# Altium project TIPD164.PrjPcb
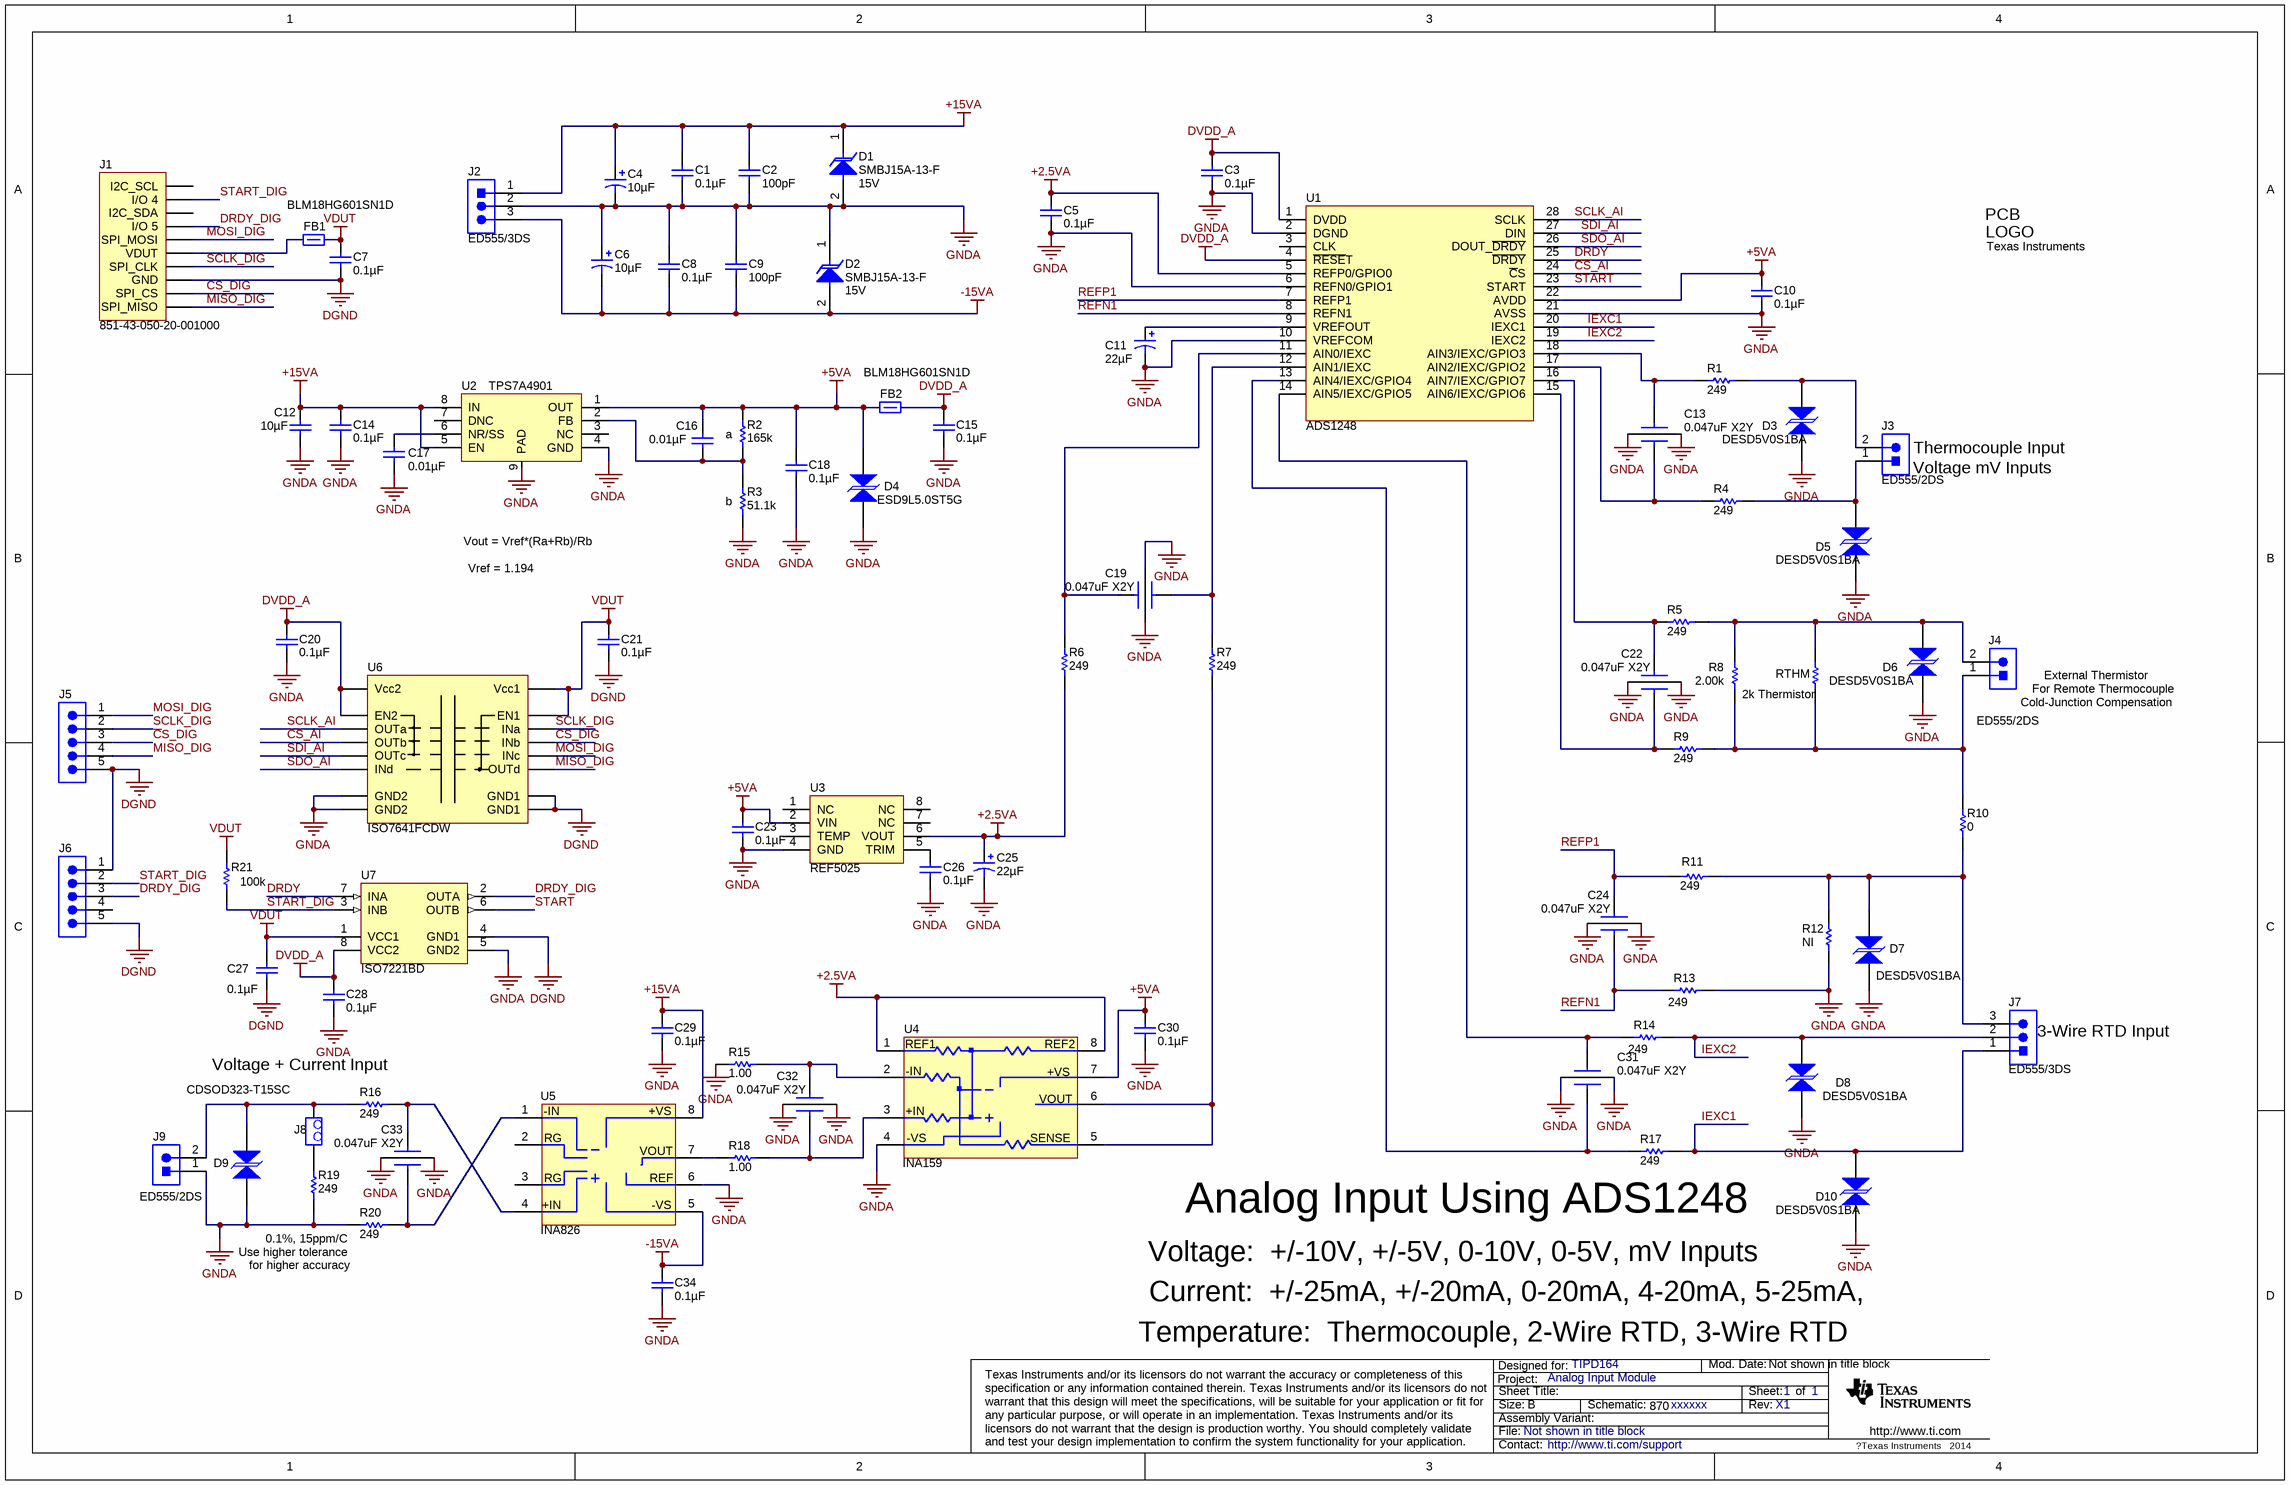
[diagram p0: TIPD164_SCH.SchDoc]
TechSupport: http://www.ti.com/support; SCH_Rev: X1; PRJ_Title: Analog Input Module; PRJ_Customer: TIPD164; PRJ_BasePN: xxxxxx; PCB_SilkRev: REV A; PCB_CopperRev: 001; CopyrightYear: 2014
1 sheet, 85 parts. Net scope: global (net labels, ports and power ports of the same name join across sheets).
Board file: TIPD164_PCB.PcbDoc

## Sheet TIPD164_SCH.SchDoc
size 431 x 279 mm; Date: Not shown in title block; ApprovedBy: Not shown in title block; CheckedBy: Not shown in title block; Author: Not shown in title block; CompanyName: Not shown in title block; DrawnBy: Not shown in title block; Engineer: Not shown in title block; Organization: Not shown in title block; Address1: Not shown in title block; Address2: Not shown in title block; Address3: Not shown in title block; Address4: Not shown in title block; DocumentNumber: 1; Revision: A; SheetNumber: 1; SheetTotal: 1; PageSetup: Record=PageOptions|CenterHorizontal=True|CenterVertical=True|PrintScale=0.62|XCorrection=1.00|YCorrection=1.00|PrintKind=0|BorderSize=5000000|LeftOffset=0|BottomOffset=0|Orientation=2|PaperLength=1000|PaperWidth=1000|Scale=100|PaperSource=15|PrintQuality=600|MediaType=1|DitherType=10|PaperKind=Letter|PrintScaleMode=1

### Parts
C1  ValueDisplayed: 0.1µF  [0603]  (hidden comment: GRM188R71H104KA93D)
C2  ValueDisplayed: 100pF  [0603]  (hidden comment: 06035A101JAT2A)
C3  ValueDisplayed: 0.1µF  [0603]  (hidden comment: GRM188R71H104KA93D)
C4  ValueDisplayed: 10µF  [7343-43]  (hidden comment: 293D106X9050E2TE3)
C5  ValueDisplayed: 0.1µF  [0603]  (hidden comment: GRM188R71H104KA93D)
C6  ValueDisplayed: 10µF  [7343-43]  (hidden comment: 293D106X9050E2TE3)
C7  ValueDisplayed: 0.1µF  [0603]  (hidden comment: GRM188R71H104KA93D)
C8  ValueDisplayed: 0.1µF  [0603]  (hidden comment: GRM188R71H104KA93D)
C9  ValueDisplayed: 100pF  [0603]  (hidden comment: 06035A101JAT2A)
C10  ValueDisplayed: 0.1µF  [0603]  (hidden comment: GRM188R71H104KA93D)
C11  ValueDisplayed: 22µF  [6032-28]  (hidden comment: 293D226X9010C2TE3)
C12  ValueDisplayed: 10µF  [1210]  (hidden comment: C3225X7R1E106M)
C13  0.047uF X2Y  [X2Y_0603]
C14  ValueDisplayed: 0.1µF  [0603]  (hidden comment: GRM188R71H104KA93D)
C15  ValueDisplayed: 0.1µF  [0603]  (hidden comment: GRM188R71H104KA93D)
C16  ValueDisplayed: 0.01µF  [0603]  (hidden comment: C0603C103J5RACTU)
C17  ValueDisplayed: 0.01µF  [0603]  (hidden comment: C0603C103J5RACTU)
C18  ValueDisplayed: 0.1µF  [0603]  (hidden comment: GRM188R71H104KA93D)
C19  0.047uF X2Y  [X2Y_0603]
C20  ValueDisplayed: 0.1µF  [0603]  (hidden comment: GRM188R71H104KA93D)
C21  ValueDisplayed: 0.1µF  [0603]  (hidden comment: GRM188R71H104KA93D)
C22  0.047uF X2Y  [X2Y_0603]
C23  ValueDisplayed: 0.1µF  [0603]  (hidden comment: GRM188R71H104KA93D)
C24  0.047uF X2Y  [X2Y_0603]
C25  ValueDisplayed: 22µF  [6032-28]  (hidden comment: 293D226X9010C2TE3)
C26  ValueDisplayed: 0.1µF  [0603]  (hidden comment: GRM188R71H104KA93D)
C27  ValueDisplayed: 0.1µF  [0603]  (hidden comment: GRM188R71H104KA93D)
C28  ValueDisplayed: 0.1µF  [0603]  (hidden comment: GRM188R71H104KA93D)
C29  ValueDisplayed: 0.1µF  [0603]  (hidden comment: GRM188R71H104KA93D)
C30  ValueDisplayed: 0.1µF  [0603]  (hidden comment: GRM188R71H104KA93D)
C31  0.047uF X2Y  [X2Y_0603]
C32  0.047uF X2Y  [X2Y_0603]
C33  0.047uF X2Y  [X2Y_0603]
C34  ValueDisplayed: 0.1µF  [0603]  (hidden comment: GRM188R71H104KA93D)
D1  SMBJ15A-13-F  value 15V  [SMB]
D2  SMBJ15A-13-F  value 15V  [SMB]
D3  DESD5V0S1BA  [SOD-323]
D4  ESD9L5.0ST5G  [SOD-923]
D5  DESD5V0S1BA  [SOD-323]
D6  DESD5V0S1BA  [SOD-323]
D7  DESD5V0S1BA  [SOD-323]
D8  DESD5V0S1BA  [SOD-323]
D9  CDSOD323-T15SC  [sod-323]
D10  DESD5V0S1BA  [SOD-323]
FB1  BLM18HG601SN1D  [0603]
FB2  BLM18HG601SN1D  [0603]
J1  851-43-050-20-001000  [851-43-010-20-001000]
J2  ED555/3DS  [TERM_BLK_ED555-3DS]
J3  ED555/2DS  [TERM_BLK_ED555-2DS]
J4  ED555/2DS  [TERM_BLK_ED555-2DS]
J5  TSW-105-07-G-S  [TSW-105-07-G-S]  (value not drawn)
J6  TSW-105-07-G-S  [TSW-105-07-G-S]  (value not drawn)
J7  ED555/3DS  [TERM_BLK_ED555-3DS]
J8  TMS-102-02-G-S  [50mil Header]  (value not drawn)
J9  ED555/2DS  [TERM_BLK_ED555-2DS]
Logo?  Texas Instruments  [TI_Stacked_Overlay_Small]  (no BOM)
R1  value 249  [0603]  (hidden comment: CRCW0603249RFKEA)
R2  value 165k  [0603]  (hidden comment: ERA-3AEB1653V)
R3  value 51.1k  [0603]  (hidden comment: RG1608P-5112-B-T5)
R4  value 249  [0603]  (hidden comment: CRCW0603249RFKEA)
R5  value 249  [0603]  (hidden comment: RG1608P-2490-B-T5)
R6  value 249  [0603]  (hidden comment: CRCW0603249RFKEA)
R7  value 249  [0603]  (hidden comment: CRCW0603249RFKEA)
R8  value 2.00k  [0603]  (hidden comment: RG1608P-202-B-T5)
R9  value 249  [0603]  (hidden comment: RG1608P-2490-B-T5)
R10  value 0  [0603]  (hidden comment: CRCW06030000Z0EA)
R11  value 249  [0603]  (hidden comment: CRCW0603249RFKEA)
R12  value NI  [0603_HV]
R13  value 249  [0603]  (hidden comment: CRCW0603249RFKEA)
R14  value 249  [0603]  (hidden comment: CRCW0603249RFKEA)
R15  value 1.00  [0603]  (hidden comment: MCT06030C1008FP500)
R16  value 249  [0603]  (hidden comment: CRCW0603249RFKEA)
R17  value 249  [0603]  (hidden comment: CRCW0603249RFKEA)
R18  value 1.00  [0603]  (hidden comment: MCT06030C1008FP500)
R19  value 249  [2010]  (hidden comment: RT2010BKC07249RL)
R20  value 249  [0603]  (hidden comment: CRCW0603249RFKEA)
R21  value 100k  [0603]  (hidden comment: CRCW0603100KFKEA)
RTHM  value 2k Thermistor  [0603]  (hidden comment: NTCS0603E3202JLT)
U1  ADS1248  [MTC28_N]
U2  TPS7A4901  [MUY08A_N]
U3  REF5025  [MUA08A_N]
U4  INA159  [MUA08A_N]
U5  INA826  [MUA08A_N]
U6  ISO7641FCDW  [M16B_N]
U7  ISO7221BD  [D0008A_N]

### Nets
+2.5VA: C5.1 C25.1(+) R6.1 U1.5(REFP0/GPIO0) U3.6(VOUT) U4.1(REF1) U4.8(REF2)
+5VA: C10.1 C16.1 C18.1 C23.1 C30.1 D4.2 FB2.1 R2.1 U1.22(AVDD) U2.1(OUT) U3.2(VIN) U4.7(VOUT)
+15VA: C1.2 C2.1 C4.1(+) C12.1 C14.1 C29.1 D1.1(K) J2.1 U2.5(EN) U2.8(IN) U5.8(+VS)
-15VA: C6.2(-) C8.1 C9.2 C34.1 D2.2(A) J2.3 U5.5(-VS)
DGND: C7.2 C21.2 C27.2 J1.8(GND) J5.5 J6.1 J6.5 U6.2(GND1) U6.8(GND1) U7.4(GND1)
DVDD_A: C3.1 C15.1 C20.1 C28.1 FB2.2 U1.1(DVDD) U1.4(~{RESE}T) U6.10(EN2) U6.16(Vcc2) U7.8(VCC2)
GNDA: C1.1 C2.2 C3.2 C4.2(-) C5.2 C6.1(+) C8.2 C9.1 C10.2 C11.2(-) C12.2 C13.3 C13.4 C14.2 C15.2 C17.2 C18.2 C19.3 C19.4 C20.2 C22.3 C22.4 C23.2 C24.3 C24.4 C25.2(-) C26.2 C28.2 C29.2 C30.2 C31.3 C31.4 C32.3 C32.4 C33.3 C33.4 C34.2 D1.2(A) D2.1(K) D3.2 D4.1 D5.2 D6.2 D7.2 D8.2 D9.2 D10.2 J2.2 J9.1 R3.1 R12.2 R13.2 R15.1 R19.1 R20.1 U1.2(DGND) U1.6(REFN0/GPIO1) U1.10(VREFCOM) U1.21(AVSS) U2.4(GND) U2.9(PAD) U3.4(GND) U4.4(V-) U5.6(REF) U6.9(GND2) U6.15(GND2) U7.5(GND2)
VDUT: C7.1 C21.1 C27.1 FB1.2 R21.2 U6.1(Vcc1) U6.7(EN1) U7.1(VCC1)
~{C}S_DIG: J1.9(SPI_CS) J5.3 U6.4(INb)
~{CS}_AI: U1.24(~{C}S) U6.13(OUTb)
DRDY: U1.25(~{DRDY}) U7.7(INA)
DRDY_DIG: J1.4(I/O_5) J6.3 U7.2(OUTA)
IEXC1: D10.1 J7.1 R17.2 U1.20(IEXC1)
IEXC2: D8.1 J7.2 R14.2 U1.19(IEXC2)
MISO_DIG: J1.10(SPI_MISO) J5.4 U6.6(OUTd)
MOSI_DIG: J1.5(SPI_MOSI) J5.1 U6.5(INc)
REFN1: C24.2 R13.1 U1.8(REFN1)
REFP1: C24.1 R11.1 U1.7(REFP1)
SCLK_AI: U1.28(SCLK) U6.14(OUTa)
SCLK_DIG: J1.7(SPI_CLK) J5.2 U6.3(INa)
SDI_AI: U1.27(DIN) U6.12(OUTc)
SDO_AI: U1.26(DOUT_~{DRDY}) U6.11(INd)
START: U1.23(START) U7.6(OUTB)
START_DIG: J1.2(I/O_4) J6.2 R21.1 U7.3(INB)
NetC11_1: C11.1(+) U1.9(VREFOUT)
NetC13_1: C13.1 R1.1 U1.18(AIN3/IEXC/GPIO3)
NetC13_2: C13.2 R4.1 U1.17(AIN2/IEXC/GPIO2)
NetC16_2: C16.2 R2.2 R3.2 U2.2(FB)
NetC17_1: C17.1 U2.6(NR/SS)
NetC19_1: C19.1 R7.2 U1.12(AIN1/IEXC)
NetC19_2: C19.2 R6.2 U1.11(AIN0/IEXC)
NetC22_1: C22.1 R5.1 U1.16(AIN7/IEXC/GPIO7)
NetC22_2: C22.2 R9.1 U1.15(AIN6/IEXC/GPIO6)
NetC26_1: C26.1 U3.5(TRIM)
NetC31_1: C31.1 R14.1 U1.14(AIN5/IEXC/GPIO5)
NetC31_2: C31.2 R17.1 U1.13(AIN4/IEXC/GPIO4)
NetC32_1: C32.1 R15.2 U4.2(-IN)
NetC32_2: C32.2 R18.2 U4.3(+IN)
NetC33_1: C33.1 R16.2 U5.4(+IN)
NetC33_2: C33.2 R20.2 U5.1(-IN)
NetD3_1: D3.1 J3.2 R1.2
NetD5_1: D5.1 J3.1 R4.2
NetD6_1: D6.1 J4.2 R5.2 R8.2 RTHM.2
NetD7_1: D7.1 J7.3 R10.1 R11.2 R12.1
NetD9_1: D9.1 J8.1 J9.2 R16.1
NetFB1_1: FB1.1 J1.6(VDUT)
NetJ4_1: J4.1 R8.1 R9.2 R10.2 RTHM.1
NetJ8_2: J8.2 R19.2
NetR7_1: R7.1 U4.5(SENSE) U4.6(OUT)
NetR18_1: R18.1 U5.7(VOUT)

Not connected (* = marked no-connect by the designer): J1 1(I2C_SCL) 3(I2C_SDA); J6 4; U1 3(CLK); U2 3(NC) 7(DNC); U3 1(NC) 3(TEMP) 7(NC) 8(NC); U5 2(RG) 3(RG)

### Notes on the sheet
- (near R2) a
- (near R3) b
- (near J3) Voltage mV Inputs
- (near J3) Thermocouple Input
- Vref = 1.194
- Vout = Vref*(Ra+Rb)/Rb
- (near J4) External Thermistor
- (near J4) Cold-Junction Compensation
- (near J4) For Remote Thermocouple
- (near J7) 3-Wire RTD Input
- Voltage + Current Input
- (near R20) 0.1%, 15ppm/C
- (near R17) Analog Input Using ADS1248
- (near R20) Use higher tolerance
- (near R20) for higher accuracy
- Voltage:  +/-10V, +/-5V, 0-10V, 0-5V, mV Inputs
- Current:  +/-25mA, +/-20mA, 0-20mA, 4-20mA, 5-25mA,
- Temperature:  Thermocouple, 2-Wire RTD, 3-Wire RTD

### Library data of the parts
C1 C3 C5 C7 C8 C10 C14 C15 C18 C20 C21 C23 C26-C30 C34 = GRM188R71H104KA93D: CAP, CERM, 0.1uF, 50V, +/-10%, X7R, 0603; Manufacturer: MuRata; Polarized: N; CompType: Capacitor; U/M: EA; Cap_F: 0.0000001; Tolerance_%: 10; VDC_V: 50; TaMin_C: -55; TaMax_C: 125
C2 C9 = 06035A101JAT2A: CAP, CERM, 100pF, 50V, +/-5%, C0G/NP0, 0603; Manufacturer: AVX; Polarized: N; CompType: Capacitor; U/M: EA; Cap_F: 0.0000000001; Tolerance_%: 5; ESR_Ohm: 0.119; Value1: 0.119 ohm; VDC_V: 50; TaMin_C: -55; TaMax_C: 125
C4 C6 = 293D106X9050E2TE3: CAP, TANT, 10uF, 50V, +/-10%, 0.8 ohm, 7343-43 SMD; Manufacturer: Vishay-Sprague; Polarized: Y; CompType: Capacitor; U/M: EA; Cap_F: 0.00001; Tolerance_%: 10; Value1: 0.8 ohm; VDC_V: 50; ESR_Ohm: 0.8; IRMS_A: 0.45; TaMin_C: -55; TaMax_C: 125; Cap_Case: E
C11 C25 = 293D226X9010C2TE3: CAP, TANT, 22uF, 10V, +/-10%, 1.5 ohm, 6032-28 SMD; Manufacturer: Vishay-Sprague; Polarized: Y; CompType: Capacitor; U/M: EA; Cap_F: 0.000022; Tolerance_%: 10; Value1: 1.5 ohm; ESR_Ohm: 1.5; IRMS_A: 0.27; TaMin_C: -55; TaMax_C: 125; Cap_Case: C
C12 = C3225X7R1E106M: CAP, CERM, 10uF, 25V, +/-20%, X7R, 1210; Manufacturer: TDK; Polarized: N; CompType: Capacitor; U/M: EA; Cap_F: 0.00001; Tolerance_%: 20; ESR_Ohm: 0.0027; Value1: 0.0027 ohm; VDC_V: 25; IRMS_A: 3; TaMin_C: -55; TaMax_C: 125
C13 C19 C22 C24 C31-C33 = X2Y Capacitor: CAP CER 0.047UF 16V 20% X7R 0603; Manufacturer: Johanson Dielectrics Inc; PartNumber: 160X14W473MV4T; U/M: EA; TaMax_C: 125; TaMin_C: -55; Tolerance%: +/-20
C16 C17 = C0603C103J5RACTU: CAP, CERM, 0.01uF, 50V, +/-5%, X7R, 0603; Manufacturer: Kemet; Polarized: N; CompType: Capacitor; U/M: EA; Cap_F: 0.00000001; Tolerance_%: 5; VDC_V: 50; TaMin_C: -55; TaMax_C: 125
D1 D2 = SMBJ15A-13-F: Diode, TVS, Uni, 15V, 600W, SMB; Manufacturer: Diodes Inc.; U/M: EA; Power_W: 5; Vr_V: 15; Value1: 5W
D3 D5-D8 D10 = SMAJ15CA: DIODE TVS 5.0V 130W; Manufacturer: Diodes.inc; SymbolCreator: Use LDAP id; U/M: EA, IN, or GM
D4 = SMAJ15CA: TVS ESD PROT ULT LOW CAP SOD-923; Manufacturer: ON Semiconductor; SymbolVersion: use current date i.e. 2008-05-20; SymbolCreator: Use LDAP id; U/M: EA, IN, or GM
D9 = SMAJ15CA: DIODE TVS ARRAY 15V SOD323; Manufacturer: Bourns; SymbolVersion: use current date i.e. 2008-05-20; SymbolCreator: Use LDAP id; U/M: EA, IN, or GM
FB1 FB2 = Ferrite_Bead: FERRITE CHIP 600 OHM 200MA 0603; Manufacturer: MuRata; U/M: EA
J1 = SM-USB-DIG-CONN: CONN SOCKET 50PIN .050 R/A SNGL; Manufacturer: Mill-Max Manufacturing Corp.; SymbolCreator: Use LDAP id; U/M: EA, IN, or GM
J2 J7 = ED555/3DS: Terminal Block, 6A, 3.5mm Pitch, 3-Pos, TH; Manufacturer: On-Shore Technology; SymbolCreator: a0799628; CompType: Connector; U/M: EA
J3 J4 J9 = ED555/2DS: Terminal Block, 6A, 3.5mm Pitch, 2-Pos, TH; Manufacturer: On-Shore Technology; SymbolCreator: a0412235; CompType: Connector; U/M: EA
J5 J6 = TSW-105-07-G-S: Header, TH, 100mil, 5x1, Gold plated, 230 mil above insulator; Manufacturer: Samtec, Inc.; SymbolCreator: a0412235; U/M: EA
J8 = Shunt: CONN HEADER 2POS .050" T/H GOLD; Manufacturer: Samtec; SymbolVersion: use current date i.e. 2008-05-20; SymbolCreator: Use LDAP id; CompType: JMP; U/M: EA, IN, or GM
Logo? = TI_Logo: Texas Instrument Corporate Signature; SymbolCreator: a0412235
R1 R4 R6 R7 R11 R13 R14 R16 R17 R20 = CRCW0603249RFKEA: RES, 249 ohm, 1%, 0.1W, 0603; Manufacturer: Vishay-Dale; CompType: Resistor; Value_Code: 249R; Tolerance_%: 1; Power_W: 0.1; VDC_V: 75; TempCo: 100 ppm/C; EIA_Code: E96; U/M: EA
R2 = RT0603BRD07164KL: RES 165K OHM 1/10W .1% 0603 SMD; Manufacturer: Panasonic Electronic Components; CompType: Resistor; Res_ohm: 165000; Tolerance_%: 0.1; Value1: 0.1%; Value2: 0.1W; VDC_V: 75; TempCo: 25 ppm/C; EIA_Code: E192; U/M: EA
R3 = RG1608P-5112-B-T5: RES, 51.1k ohm, 0.1%, 0.1W, 0603; Manufacturer: Susumu Co Ltd; CompType: Resistor; Res_ohm: 51100; Value_Code: 51k1; Tolerance_%: 0.1; VDC_V: 75; TempCo: 25 ppm/C; EIA_Code: E192; U/M: EA
R5 = CRCW0603249RFKEA: RES 249 OHM 1/10W .1% 0603 SMD; Manufacturer: Susumu; CompType: Resistor; Value_Code: 249R; Tolerance_%: 0.1; VDC_V: 75; TempCo: 25 ppm/C; EIA_Code: E96; U/M: EA
R8 = RG1608P-202-B-T5: RES, 2.00k ohm, 0.1%, 0.1W, 0603; Manufacturer: Susumu Co Ltd; CompType: Resistor; Res_ohm: 2000; Value_Code: 2k00; Tolerance_%: 0.1; VDC_V: 75; TempCo: 25 ppm/C; EIA_Code: E192; U/M: EA
R9 = CRCW0603249RFKEA: RES 249 OHM 1/10W .1% 0603 SMD; Manufacturer: Susumu; CompType: Resistor; Value_Code: 249R; Tolerance_%: 0.1; Value1: 0.1%; Value2: 0.1W; VDC_V: 75; TempCo: 25 ppm/C; EIA_Code: E96; U/M: EA
R10 = CRCW06030000Z0EA: RES, 0 ohm, 5%, 0.1W, 0603; Manufacturer: Vishay-Dale; CompType: Resistor; Value_Code: 0000; Tolerance_%: 5; Power_W: 0.1; VDC_V: 75; TempCo: 200 ppm/C; EIA_Code: E24; U/M: EA
R12 = RC0603FR-078K2L: NI; CompType: Resistor; Res_ohm: 8200; Value_Code: 8k20; Tolerance_%: 1; Value1: 0.2%; Power_W: 0.1; Value2: 0.125W; VDC_V: 150; TempCo: 5 ppm/C; U/M: EA
R15 R18 = CRCW06031R00FKEA: RES 1.00 OHM 1/8W 1% SMD 0603; Manufacturer: Vishay Beyschlag; CompType: Resistor; Res_ohm: 1; Value_Code: 1R00; Power_W: 0.125; Value2: 0.1W; VDC_V: 75; TempCo: 50 ppm/C; EIA_Code: E96; U/M: EA
R19 = CRCW1206249RFKEA: RES 249 OHM 1/2W .1% 2010 SMD; Manufacturer: Yageo; Upgrade PartNumber: PLTT250ACT-ND; Upgrade Manufacturer: Vishay Thin Film; CompType: Resistor; Value_Code: 249R; Tolerance_%: 0.1; Value1: 1%; Power_W: 0.5; Value2: 0.25W; VDC_V: 200; TempCo: +/-15 ppm/C; EIA_Code: E96; U/M: EA; Upgrade Specs: 0.02%, 5ppm
R21 = CRCW0603100KFKEA: RES, 100k ohm, 1%, 0.1W, 0603; Manufacturer: Vishay-Dale; CompType: Resistor; Res_ohm: 100000; Tolerance_%: 1; Power_W: 0.1; VDC_V: 75; TempCo: 100 ppm/C; EIA_Code: E96; U/M: EA
RTHM = CRCW0603100KJNEA: THERMISTOR NTC 2K 5% 0603; Manufacturer: Vishay-Dale; CompType: Resistor; Tolerance_%: 5; Power_W: 0.1; Value2: 0.1W; VDC_V: 75; EIA_Code: E24; U/M: EA
U1 = ADS1248: IC ADC 24BIT DEL/SIG LN 28TSSOP; Manufacturer: Texas Instruments Inc; PartNumber: ADS1248IPW; SymbolVersion: use current date i.e. 2008-05-20; SymbolCreator: Use LDAP id; U/M: EA, IN, or GM
U2 = TPS7A4901: IC REG LDO ADJ .15A 8MSOP; Manufacturer: Texas Instruments Inc; PartNumber: TPS7A4901DGNR; SymbolVersion: use current date i.e. 2008-05-20; SymbolCreator: Use LDAP id; CompType: TPS; U/M: EA, IN, or GM
U3 = REF5025: IC VREF SERIES PREC 2.5V 8-MSOP; Manufacturer: Texas Instruments Inc; PartNumber: REF5025IDGKT; SymbolVersion: use current date i.e. 2008-05-20; SymbolCreator: Use LDAP id; CompType: REF; U/M: EA, IN, or GM
U4 = INA159: IC OPAMP DIFF 1.5MHZ SGL 8MSOP; Manufacturer: Texas Instruments Inc; PartNumber: INA159AIDGKT; SymbolVersion: use current date i.e. 2008-05-20; SymbolCreator: Use LDAP id; CompType: Used in some BOM reports.  Useful for finding later.; U/M: EA, IN, or GM
U5 = INA826: IC OPAMP INSTR 1MHZ 8MSOP; Manufacturer: Texas Instruments Inc; PartNumber: INA826AIDGKR; SymbolVersion: use current date i.e. 2008-05-20; SymbolCreator: Use LDAP id; CompType: Used in some BOM reports.  Useful for finding later.; U/M: EA, IN, or GM
U6 = ISO7241: ISOLATOR DGTL 25MBPS 4CH 16SOIC; Manufacturer: Texas Instruments Inc; SymbolVersion: use current date i.e. 2008-05-20; SymbolCreator: Use LDAP id; CompType: Used in some BOM reports.  Useful for finding later.; U/M: EA, IN, or GM
U7 = ISO7221BD: 5 Mbps Dual Channels, 1 / 1, Digital Isolator, 3.3 V / 5 V, -40 to +125 degC, 8-pin SOIC (D), Green (RoHS & no Sb/Br); Manufacturer: Texas Instruments; Alternate Manufacturer: None; Alternate PartNumber: Equivalent; Datarate(Mbps): 5; Input Noise Filter: Yes; Insulation Rating(VRMS): 2500; Rating: Catalog; Supply Voltage(s)(V): 3.3, 5; TTL/CMOS Input Threshold: TTL

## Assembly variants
-100A: not fitted R12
